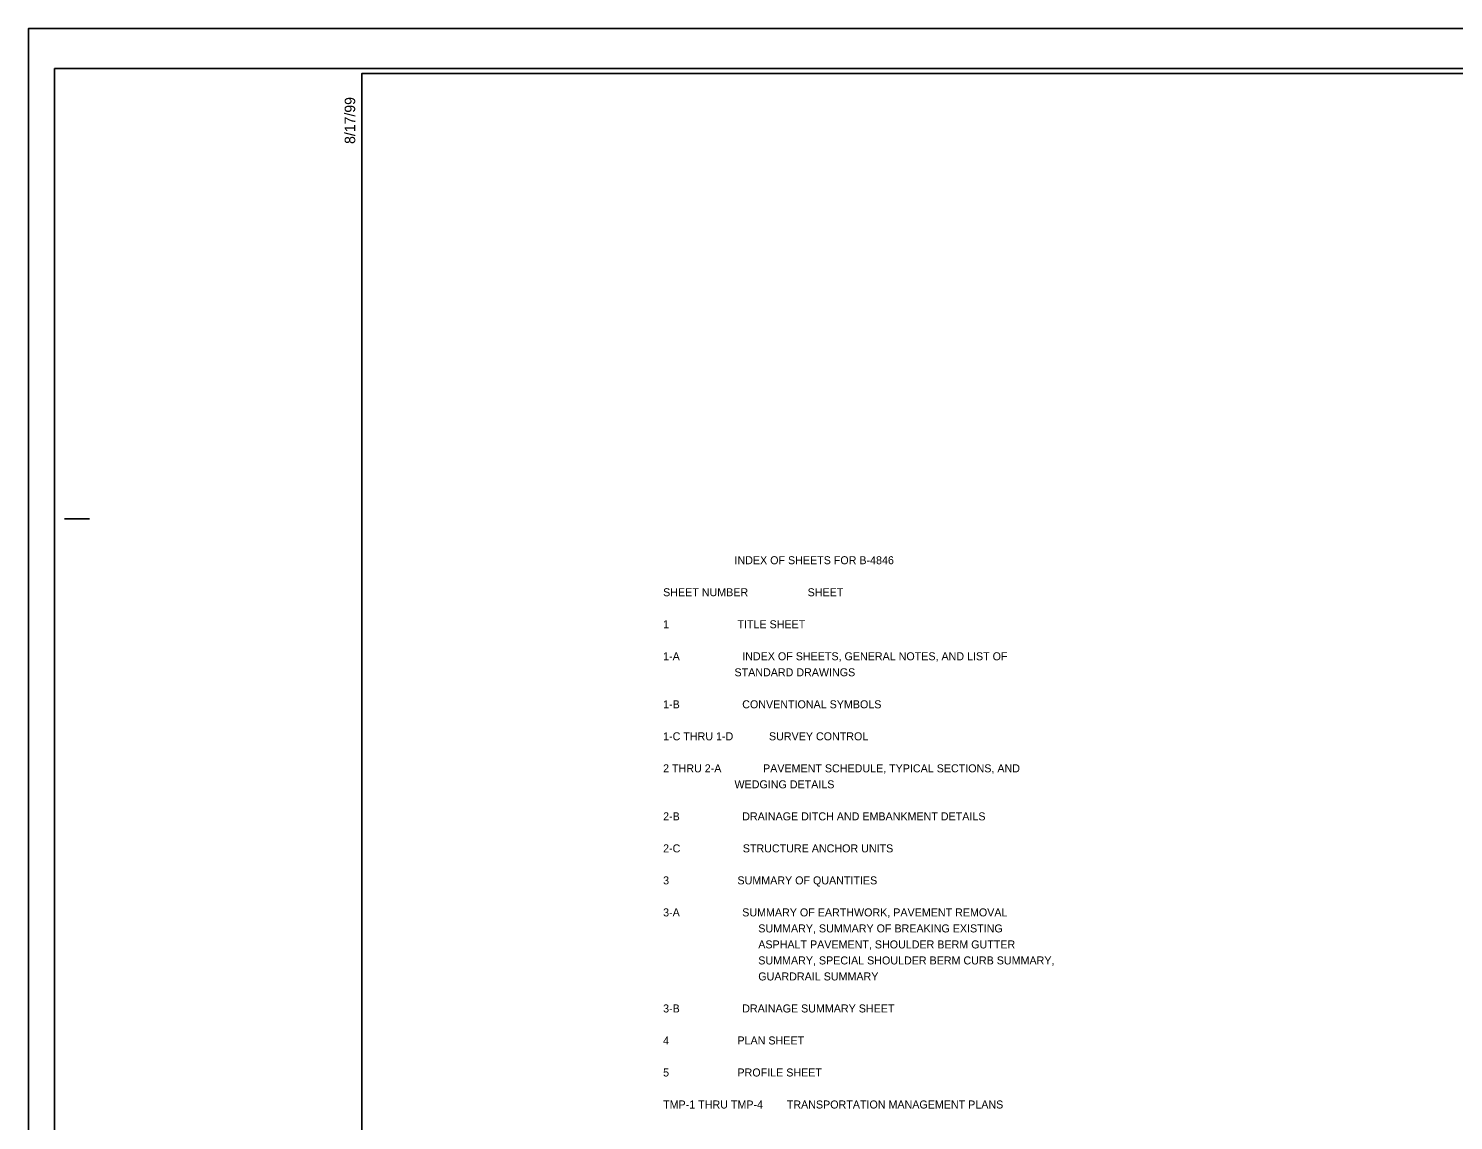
# Model space of a CAD drawing. Extents: x 573606 to 575290, y -53273 to -52178.
# Drawn here: x 573606 to 574319, y -52723 to -52178 of the extents above; entities that cross this region are included whole.
import ezdxf

# ---------------------------------------------------------------- set-up
doc = ezdxf.new("R2010")
doc.units = 0
for name, color, linetype in [('Sheet Cutting Line CELL', 7, 'Continuous'), ('Sheet Data Text CELL', 7, 'Continuous'), ('Sheet Plan CELL', 7, 'Continuous'), ('Sheet Plot Border Inside CELL', 7, 'Continuous'), ('Sheet Plot Border Outside CELL', 7, 'Continuous')]:
    doc.layers.add(name, color=color, linetype=linetype)

msp = doc.modelspace()

# ---------------------------------------------------------------- linework, layer by layer
at = {"layer": 'Sheet Cutting Line CELL'}
for p, q in [((575289.96, -52177.62), (573606.46, -52177.62)), ((573606.46, -52177.62), (573606.46, -53272.62))]:
    msp.add_line(p, q, dxfattribs=at)
at = {"layer": 'Sheet Plan CELL'}
for p, q in [((573772.96, -52200.12), (573772.96, -52200.12)), ((573624.46, -52422.62), (573636.96, -52422.62))]:
    msp.add_line(p, q, dxfattribs=at)
msp.add_lwpolyline([(575272.96, -52200.12), (573772.96, -52200.12), (573772.96, -53250.12), (575272.96, -53250.12)], close=True, dxfattribs=at)
at = {"layer": 'Sheet Plot Border Inside CELL'}
msp.add_lwpolyline([(573619.46, -53252.62), (575285.46, -53252.62), (575285.46, -52197.62), (573619.46, -52197.62)], close=True, dxfattribs=at)
at = {"layer": 'Sheet Plot Border Outside CELL'}
msp.add_lwpolyline([(573606.46, -53272.62), (575289.96, -53272.62), (575289.96, -52177.62), (573606.46, -52177.62)], close=True, dxfattribs=at)

# ---------------------------------------------------------------- texts
at = {"layer": 'Sheet Data Text CELL'}
for s, p in [('                        INDEX OF SHEETS FOR B-4846', (573923.59, -52445.36)), ('SHEET NUMBER                    SHEET   ', (573923.59, -52461.36)), ('1                       TITLE SHEET', (573923.59, -52477.36)), ('1-A                     INDEX OF SHEETS, GENERAL NOTES, AND LIST OF ', (573923.59, -52493.36)), ('                        STANDARD DRAWINGS', (573923.59, -52501.36)), ('1-B                     CONVENTIONAL SYMBOLS', (573923.59, -52517.36)), ('1-C THRU 1-D            SURVEY CONTROL ', (573923.59, -52533.36)), ('2 THRU 2-A              PAVEMENT SCHEDULE, TYPICAL SECTIONS, AND ', (573923.59, -52549.36)), ('                        WEDGING DETAILS ', (573923.59, -52557.36)), ('2-B                     DRAINAGE DITCH AND EMBANKMENT DETAILS', (573923.59, -52573.36)), ('2-C                     STRUCTURE ANCHOR UNITS', (573923.59, -52589.36)), ('3                       SUMMARY OF QUANTITIES ', (573923.59, -52605.36)), ('3-A                     SUMMARY OF EARTHWORK, PAVEMENT REMOVAL ', (573923.59, -52621.36)), ('                                SUMMARY, SUMMARY OF BREAKING EXISTING', (573923.59, -52629.36)), ('                                ASPHALT PAVEMENT, SHOULDER BERM GUTTER', (573923.59, -52637.36)), ('                                SUMMARY, SPECIAL SHOULDER BERM CURB SUMMARY,', (573923.59, -52645.36)), ('                                GUARDRAIL SUMMARY', (573923.59, -52653.36)), ('3-B                     DRAINAGE SUMMARY SHEET ', (573923.59, -52669.36)), ('4                       PLAN SHEET', (573923.59, -52685.36)), ('5                       PROFILE SHEET  ', (573923.59, -52701.36)), ('TMP-1 THRU TMP-4        TRANSPORTATION MANAGEMENT PLANS', (573923.59, -52717.36))]:
    msp.add_text(s, height=4, dxfattribs=at).set_placement(p)
at = {"layer": 'Sheet Plan CELL'}
msp.add_text('8/17/99', height=5.25, rotation=90, dxfattribs=at).set_placement((573769.71, -52235.32))

doc.saveas('drawing.dxf')
